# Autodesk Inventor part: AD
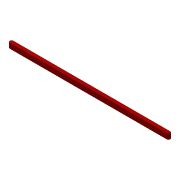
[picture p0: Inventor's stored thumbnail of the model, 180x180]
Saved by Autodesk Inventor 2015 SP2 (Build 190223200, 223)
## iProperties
Created: 2019-08
Part Number: AD
Material: 一般
Document SubType Name: Modeling
Designer: Kuan_Lun Hsu
Density: 1 g/cm^3
Appearance: 平滑 - 紅色
Mass: 0.93927 g
Surface Area: 13.3069 cm^2
Volume: 0.93927 cm^3
Author: Kuan_Lun Hsu
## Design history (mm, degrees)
sketch "草圖1"
  geometry: L1 (0, 0)-(90, 0); L2 (0, -2.5)-(90, -2.5); L3 (90, 2.5)-(0, 2.5); A1 r 2.5 centre (0, 0) between (0, 2.5) and (0, -2.5); A2 r 2.5 centre (90, 0) between (90, -2.5) and (90, 2.5); 1 further point
  constraints: 8 end point, 4 point on circle, 4 tangent, 2 centre point, 1 horizontal, 1 midpoint, 1 parallel
  dimensions: "d0" = 90 distance of L1.start L1.end (= AD_); "d1" = 5 distance between parallel lines of L2 L3 (= w_)
extrude "擠出1" new body sketch "草圖1" distance "d2" = 2 (= t_); taper "d3" = 0 deg
node "實體1"
other parameters: "AD_" = 90 [user parameter; used in 1 equation term], "w_" = 5 [user parameter; used in 1 equation term], "t_" = 2 [user parameter; used in 1 equation term]
